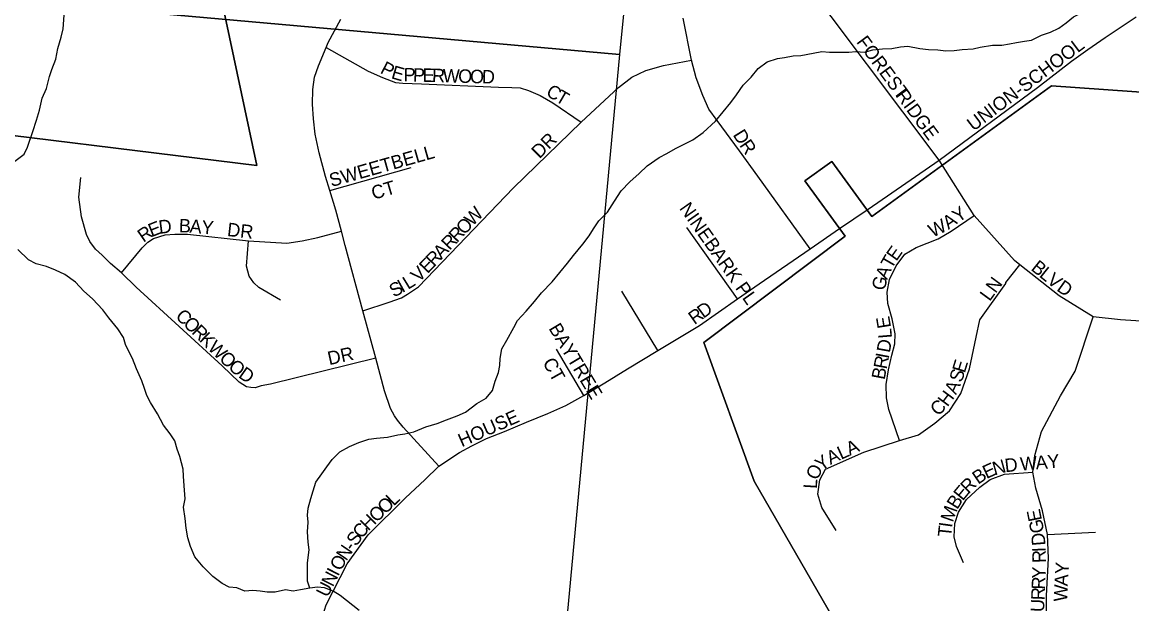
# Model space of a CAD drawing. Extents: x 0 to 680, y 0 to 440.
# Drawn here: x 81.15 to 93.33, y 190.49 to 196.88 of the extents above; entities that cross this region are included whole.
import ezdxf

# ---------------------------------------------------------------- set-up
doc = ezdxf.new("R2010")
doc.units = 0
for name, color, linetype in [('GM_X_City_Street', 7, 'Continuous'), ('GM_X_City_Street_Text', 7, 'Continuous'), ('GM_X_Corporation', 7, 'Continuous'), ('GM_X_Minor_River', 7, 'Continuous'), ('GM_X_Section', 7, 'Continuous')]:
    doc.layers.add(name, color=color, linetype=linetype)

msp = doc.modelspace()

# ---------------------------------------------------------------- linework, layer by layer
at = {"layer": 'GM_X_City_Street'}
for points in [[(91.221, 195.363), (89.636, 197.477), (89.55, 197.598), (88.772, 198.692), (88.323, 199.318), (87.854, 199.993), (87.693, 200.211), (87.593, 200.353), (87.475, 200.491), (87.323, 200.642), (87.18, 200.757), (87.014, 200.885), (86.894, 200.969), (86.863, 200.985), (86.732, 201.055), (86.598, 201.11), (86.411, 201.179), (86.075, 201.245), (85.679, 201.302), (84.892, 201.379), (83.88, 201.481), (83.451, 201.525)], [(85.727, 192.002), (85.336, 192.432), (85.275, 192.507), (85.242, 192.557), (85.198, 192.636), (85.131, 192.831), (85.034, 193.19), (84.893, 193.71), (84.699, 194.428), (84.657, 194.583), (84.595, 194.815), (84.53, 195.03), (84.483, 195.185), (84.414, 195.445), (84.371, 195.65), (84.351, 195.818), (84.341, 195.98), (84.344, 196.141), (84.363, 196.277), (84.405, 196.4), (84.491, 196.602), (84.514, 196.657), (84.652, 196.913)], [(89.804, 194.39), (89.228, 195.189), (89.027, 195.465), (88.782, 195.801), (88.69, 195.923), (88.626, 196.075), (88.553, 196.27), (88.501, 196.462), (88.41, 196.923)], [(90.438, 194.826), (91.221, 195.363), (92.298, 196.161), (92.671, 196.451), (92.85, 196.579), (93.042, 196.712), (93.381, 196.939)], [(84.491, 196.602), (84.95, 196.341), (85.107, 196.273), (85.253, 196.218), (85.33, 196.208), (85.538, 196.203), (86.381, 196.164), (86.53, 196.162), (86.619, 196.158), (86.712, 196.129), (86.841, 196.074), (86.979, 195.995), (87.288, 195.781)], [(84.893, 193.71), (85.183, 193.806), (85.317, 193.853), (85.384, 193.891), (85.502, 193.974), (86.546, 195.059), (87.288, 195.781), (87.699, 196.161), (87.844, 196.277), (88, 196.347), (88.195, 196.402), (88.501, 196.462)], [(84.53, 195.03), (85.423, 195.284)], [(94.473, 192.643), (94.098, 193.121), (93.936, 193.322), (93.718, 193.512), (93.49, 193.594), (93.208, 193.61), (92.909, 193.643), (92.537, 193.873), (92.106, 194.215), (92.045, 194.263), (91.604, 194.755), (91.221, 195.363)], [(85.034, 193.19), (83.879, 192.903), (83.777, 192.885), (83.71, 192.864), (83.663, 192.867), (83.616, 192.875), (83.535, 192.927), (83.348, 193.104), (82.406, 193.971), (82.242, 194.127), (82.123, 194.231), (82.032, 194.319), (81.959, 194.388), (81.897, 194.469), (81.86, 194.549), (81.805, 194.743), (81.775, 194.959), (81.798, 195.172)], [(90.125, 194.613), (90.438, 194.826)], [(90.783, 192.285), (90.668, 192.627), (90.641, 192.753), (90.636, 192.9), (90.662, 193.063), (90.699, 193.221), (90.731, 193.347), (90.736, 193.458), (90.704, 193.621), (90.657, 193.79), (90.647, 193.916), (90.673, 194.053), (90.747, 194.205), (90.841, 194.331), (90.967, 194.405), (91.089, 194.452), (91.21, 194.5), (91.352, 194.584), (91.604, 194.755)], [(82.242, 194.127), (82.471, 194.403), (82.534, 194.465), (82.596, 194.504), (82.723, 194.545), (82.83, 194.551), (82.967, 194.55), (83.636, 194.478), (84.059, 194.454), (84.225, 194.477), (84.4, 194.516), (84.657, 194.583)], [(84.3, 189.767), (84.382, 190.128), (84.492, 190.479), (84.722, 190.93), (84.953, 191.25), (85.362, 191.654), (85.573, 191.854), (85.727, 192.002), (85.953, 192.152), (86.088, 192.225), (86.251, 192.308), (86.449, 192.385), (86.689, 192.488), (86.925, 192.583), (87.12, 192.671), (87.318, 192.779), (87.549, 192.919), (87.799, 193.074), (88.13, 193.275), (88.589, 193.548), (89.007, 193.841), (89.243, 194.007), (89.804, 194.39), (90.125, 194.613)], [(89.007, 193.841), (88.451, 194.623)], [(83.988, 193.828), (83.751, 193.965), (83.695, 194.016), (83.645, 194.09), (83.615, 194.199), (83.636, 194.478)], [(90.089, 191.295), (89.931, 191.548), (89.889, 191.695), (89.91, 191.853), (89.973, 191.969), (90.394, 192.158), (90.783, 192.285), (90.994, 192.348), (91.173, 192.474), (91.331, 192.611), (91.457, 192.8), (91.552, 193.074), (91.625, 193.421), (91.667, 193.611), (91.952, 194.01), (91.952, 194.021), (92.106, 194.215)], [(88.13, 193.275), (87.734, 193.926)], [(92.424, 189.875), (92.398, 190.297), (92.398, 190.579), (92.42, 190.992), (92.409, 191.253), (92.355, 191.514), (92.279, 191.763), (92.246, 191.937), (92.268, 192.122), (92.344, 192.383), (92.55, 192.774), (92.713, 193.045), (92.909, 193.643)], [(87.318, 192.779), (87.018, 193.287)], [(91.486, 190.943), (91.41, 191.122), (91.383, 191.226), (91.393, 191.372), (91.431, 191.497), (91.518, 191.638), (91.665, 191.774), (91.779, 191.856), (91.937, 191.916), (92.246, 191.937)], [(92.409, 191.253), (92.936, 191.28)]]:
    msp.add_lwpolyline(points, dxfattribs=at)
at = {"layer": 'GM_X_Corporation'}
for points in [[(83.951, 205.591), (83.402, 201.12), (80.239, 201.509), (79.822, 197.545), (83.345, 197.112), (83.729, 195.305), (79.918, 195.773), (79.532, 197.595), (67.969, 198.303)], [(67.969, 198.303), (79.532, 197.595), (79.918, 195.773), (83.729, 195.305), (83.345, 197.112), (79.822, 197.545), (80.239, 201.509), (83.402, 201.12), (83.951, 205.591)], [(91.033, 188.638), (89.188, 191.837), (88.635, 193.36), (90.186, 194.53), (89.746, 195.137), (90.04, 195.35), (90.48, 194.744), (92.452, 196.179), (96.031, 195.929), (96.041, 196.129), (96.855, 196.073), (96.84, 195.791), (97.973, 194.39), (99.899, 194.457), (98.982, 195.632), (103.205, 195.338)], [(101.687, 179.172), (103.205, 195.338), (98.982, 195.632), (99.899, 194.457), (97.973, 194.39), (96.84, 195.791), (96.855, 196.073), (96.041, 196.129), (96.031, 195.929), (92.452, 196.179), (90.48, 194.744), (90.04, 195.35), (89.746, 195.137), (90.186, 194.53), (88.635, 193.36), (89.188, 191.837), (91.033, 188.638)]]:
    msp.add_lwpolyline(points, dxfattribs=at)
at = {"layer": 'GM_X_Minor_River'}
for points in [[(92.615, 196.873), (92.693, 196.938), (92.788, 196.986), (92.913, 197.063), (92.99, 197.117), (93.091, 197.194), (93.294, 197.361), (93.377, 197.468)], [(81.074, 195.353), (81.175, 195.43), (81.211, 195.508), (81.27, 195.68), (81.312, 195.805), (81.342, 195.912), (81.372, 196.044), (81.419, 196.151), (81.455, 196.282), (81.479, 196.359), (81.521, 196.472), (81.544, 196.591), (81.58, 196.716), (81.604, 196.806), (81.616, 196.955)], [(84.311, 190.662), (84.287, 190.739), (84.287, 190.941), (84.305, 191.084), (84.293, 191.167), (84.287, 191.281), (84.293, 191.388), (84.287, 191.465), (84.293, 191.543), (84.323, 191.65), (84.347, 191.733), (84.377, 191.828), (84.442, 191.918), (84.496, 191.995), (84.555, 192.078), (84.639, 192.162), (84.746, 192.221), (84.847, 192.263), (84.96, 192.299), (85.043, 192.311), (85.163, 192.323), (85.276, 192.346), (85.353, 192.358), (85.454, 192.382), (85.585, 192.436), (85.71, 192.471), (85.811, 192.513), (85.93, 192.555), (86.02, 192.597), (86.145, 192.692), (86.246, 192.751), (86.317, 192.835), (86.347, 192.936), (86.383, 193.031), (86.395, 193.109), (86.401, 193.186), (86.419, 193.293), (86.472, 193.388), (86.549, 193.525), (86.591, 193.603), (86.686, 193.704), (86.776, 193.811), (86.853, 193.906), (86.972, 194.026), (87.139, 194.234), (87.204, 194.317), (87.306, 194.442), (87.377, 194.532), (87.425, 194.609), (87.484, 194.698), (87.579, 194.794), (87.657, 194.913), (87.728, 195.026), (87.824, 195.127), (87.925, 195.217), (88.014, 195.3), (88.145, 195.395), (88.228, 195.437), (88.324, 195.491), (88.514, 195.586), (88.627, 195.669), (88.764, 195.794), (88.931, 195.997), (88.996, 196.08), (89.068, 196.187), (89.157, 196.277), (89.234, 196.372), (89.33, 196.443), (89.443, 196.479), (89.52, 196.491), (89.615, 196.509), (89.699, 196.515), (89.836, 196.539), (89.931, 196.557), (90.014, 196.551), (90.228, 196.551), (90.306, 196.557), (90.401, 196.551), (90.49, 196.575), (90.597, 196.586), (90.699, 196.592), (90.794, 196.61), (90.877, 196.616), (91.008, 196.592), (91.103, 196.581), (91.205, 196.575), (91.294, 196.563), (91.383, 196.569), (91.472, 196.581), (91.591, 196.587), (91.669, 196.604), (91.806, 196.628), (91.907, 196.628), (91.99, 196.64), (92.068, 196.658), (92.157, 196.67), (92.234, 196.682), (92.341, 196.736), (92.443, 196.771), (92.532, 196.813), (92.615, 196.873)], [(84.853, 190.418), (84.644, 190.584), (84.567, 190.632), (84.472, 190.667), (84.394, 190.673), (84.311, 190.662), (84.21, 190.644), (84.127, 190.632), (84.043, 190.644), (83.93, 190.62), (83.841, 190.62), (83.764, 190.632), (83.686, 190.638), (83.597, 190.632), (83.508, 190.667), (83.424, 190.673), (83.347, 190.715), (83.246, 190.792), (83.139, 190.899), (83.049, 191.007), (83.002, 191.12), (82.972, 191.215), (82.954, 191.322), (82.942, 191.429), (82.924, 191.554), (82.942, 191.644), (82.93, 191.786), (82.925, 191.894), (82.919, 191.971), (82.883, 192.108), (82.853, 192.191), (82.829, 192.281), (82.776, 192.358), (82.704, 192.453), (82.639, 192.578), (82.562, 192.703), (82.52, 192.781), (82.496, 192.858), (82.466, 192.941), (82.407, 193.072), (82.365, 193.185), (82.324, 193.263), (82.288, 193.34), (82.264, 193.418), (82.205, 193.513), (82.103, 193.632), (82.038, 193.721), (81.925, 193.84), (81.83, 193.924), (81.74, 194.025), (81.621, 194.108), (81.52, 194.156), (81.419, 194.198), (81.306, 194.227), (81.223, 194.269), (81.104, 194.382)]]:
    msp.add_lwpolyline(points, dxfattribs=at)
at = {"layer": 'GM_X_Section'}
for points in [[(89.303, 212.485), (87.711, 196.525), (72.033, 197.922), (73.628, 213.785)], [(87.711, 196.525), (86.234, 180.729), (70.5, 182.241), (72.033, 197.922)]]:
    msp.add_lwpolyline(points, close=True, dxfattribs=at)

# ---------------------------------------------------------------- texts
at = {"layer": 'GM_X_City_Street_Text'}
for s, height, rotation, p in [('FOREST', 0.1482, 306.4294, (90.305, 196.662)), ('UNION-SCHOOL', 0.14823, 36.9771, (91.596, 195.677)), ('P', 0.148, 332.4577, (85.074, 196.326)), ('E', 0.148, 343.8402, (85.196, 196.265)), ('P', 0.148, 358.6381, (85.338, 196.23)), ('P', 0.148, 358.4696, (85.442, 196.227)), ('E', 0.148, 358.5497, (85.546, 196.225)), ('R', 0.148, 358.543, (85.651, 196.222)), ('W', 0.148, 358.5372, (85.768, 196.219)), ('O', 0.148, 358.5628, (85.938, 196.215)), ('O', 0.148, 358.5575, (86.068, 196.211)), ('D', 0.148, 358.5357, (86.198, 196.208)), ('C', 0.148, 328.3241, (86.893, 196.082)), ('T', 0.148, 329.8525, (86.996, 196.018)), ('RIDGE', 0.1482, 306.3282, (90.735, 196.075)), ('DR', 0.1482, 45, (86.832, 195.374)), ('D', 0.148, 301.8896, (88.95, 195.643)), ('SWEETBELL', 0.1482, 15.7502, (84.548, 195.068)), ('R', 0.148, 303.831, (89.021, 195.528)), ('CT', 0.1482, 16.3944, (85.011, 194.928)), ('NINEBARK PL', 0.14823, 305.0977, (88.361, 194.835)), ('W', 0.148, 46.3938, (86.097, 194.631)), ('Y', 0.148, 35.1648, (91.429, 194.673)), ('E', 0.148, 21.7456, (82.573, 194.517)), ('D', 0.148, 7.3852, (82.661, 194.554)), ('B', 0.148, 358.3482, (82.872, 194.572)), ('A', 0.148, 355.3616, (82.987, 194.568)), ('Y', 0.148, 354.8135, (83.117, 194.558)), ('DR', 0.1482, 353.6505, (83.398, 194.532)), ('O', 0.148, 46.3911, (86.007, 194.536)), ('W', 0.148, 26.0387, (91.147, 194.511)), ('A', 0.148, 34.9396, (91.321, 194.598)), ('R', 0.148, 34.451, (82.484, 194.455)), ('R', 0.148, 46.3987, (85.846, 194.366)), ('R', 0.148, 46.4081, (85.926, 194.451)), ('A', 0.148, 46.3911, (85.756, 194.272)), ('E', 0.148, 54.529, (90.748, 194.247)), ('E', 0.148, 46.4313, (85.603, 194.111)), ('R', 0.148, 46.3913, (85.675, 194.187)), ('T', 0.148, 60.1467, (90.698, 194.16)), ('V', 0.148, 44.5691, (85.506, 194.016)), ('A', 0.148, 66.2217, (90.647, 194.044)), ('B', 0.148, 321.435, (92.218, 194.163)), ('L', 0.148, 321.4085, (92.309, 194.09)), ('I', 0.148, 29.0886, (85.325, 193.904)), ('L', 0.148, 31.5702, (85.388, 193.939)), ('G', 0.148, 76.9234, (90.62, 193.924)), ('LN', 0.1482, 53.7411, (91.773, 193.806)), ('V', 0.148, 321.4372, (92.391, 194.025)), ('D', 0.148, 324.7763, (92.5, 193.938)), ('S', 0.148, 29.0944, (85.234, 193.853)), ('D', 0.148, 36.1692, (88.631, 193.621)), ('C', 0.148, 315.7213, (82.827, 193.64)), ('R', 0.148, 35.3542, (88.533, 193.552)), ('O', 0.148, 315.7482, (82.912, 193.557)), ('R', 0.148, 315.7213, (83.005, 193.467)), ('BAYTREE', 0.1482, 300.9643, (86.928, 193.517)), ('E', 0.148, 99.2351, (90.692, 193.529)), ('K', 0.148, 315.7323, (83.089, 193.384)), ('L', 0.148, 94.7142, (90.702, 193.412)), ('W', 0.148, 315.7287, (83.182, 193.293)), ('DR', 0.1482, 12.5327, (84.524, 193.112)), ('D', 0.148, 79.9575, (90.677, 193.243)), ('O', 0.148, 317.3105, (83.307, 193.172)), ('CT', 0.1482, 299.3565, (86.862, 193.143)), ('R', 0.148, 79.1521, (90.642, 193.062)), ('I', 0.148, 79.1619, (90.664, 193.177)), ('O', 0.148, 318.9883, (83.406, 193.08)), ('D', 0.148, 324.773, (83.518, 192.985)), ('B', 0.148, 79.1521, (90.62, 192.946)), ('S', 0.148, 71.1673, (91.465, 192.915)), ('E', 0.148, 72.9291, (91.5, 193.019)), ('H', 0.148, 53.6051, (91.31, 192.648)), ('A', 0.148, 65.0874, (91.404, 192.781)), ('C', 0.148, 42.973, (91.204, 192.546)), ('HOUSE', 0.1482, 23.8399, (85.979, 192.21)), ('L', 0.148, 24.5118, (90.142, 192.072)), ('A', 0.148, 24.5018, (90.237, 192.116)), ('Y', 0.148, 36.3279, (89.926, 191.943)), ('A', 0.148, 25.6071, (90.025, 192.016)), ('D', 0.148, 6.2412, (91.946, 191.936)), ('W', 0.148, 4.7794, (92.114, 191.953)), ('A', 0.148, 4.7491, (92.283, 191.967)), ('Y', 0.148, 4.7792, (92.413, 191.978)), ('O', 0.148, 62.7311, (89.878, 191.84)), ('B', 0.148, 34.3434, (91.647, 191.798)), ('E', 0.148, 24.5728, (91.738, 191.861)), ('N', 0.148, 15.7172, (91.827, 191.902)), ('L', 0.148, 86.4185, (89.876, 191.752)), ('R', 0.148, 44.9313, (91.54, 191.693)), ('E', 0.148, 50.5722, (91.477, 191.615)), ('O', 0.148, 44.0595, (85.138, 191.469)), ('L', 0.148, 44.0704, (85.231, 191.559)), ('B', 0.148, 57.6573, (91.417, 191.52)), ('H', 0.148, 44.7991, (84.952, 191.286)), ('O', 0.148, 44.0573, (85.044, 191.378)), ('M', 0.148, 70.3094, (91.368, 191.38)), ('E', 0.148, 101.3047, (92.349, 191.412)), ('C', 0.148, 50.7977, (84.88, 191.198)), ('I', 0.148, 82.1049, (91.361, 191.323)), ('G', 0.148, 100.5468, (92.374, 191.281)), ('S', 0.148, 54.5105, (84.821, 191.115)), ('T', 0.148, 84.197, (91.35, 191.221)), ('D', 0.148, 94.7345, (92.387, 191.135)), ('N', 0.148, 55.819, (84.711, 190.955)), ('-', 0.148, 54.503, (84.783, 191.062)), ('O', 0.148, 61.5675, (84.651, 190.844)), ('I', 0.148, 92.0977, (92.389, 191.062)), ('R', 0.148, 90.7421, (92.391, 190.941)), ('I', 0.148, 63.3372, (84.622, 190.787)), ('Y', 0.148, 87.9015, (92.385, 190.764)), ('Y', 0.148, 86.3037, (92.638, 190.812)), ('N', 0.148, 63.3341, (84.563, 190.67)), ('R', 0.148, 87.9112, (92.381, 190.646)), ('A', 0.148, 86.4564, (92.63, 190.682)), ('U', 0.148, 63.347, (84.505, 190.554)), ('R', 0.148, 87.9112, (92.376, 190.529)), ('W', 0.148, 87.4944, (92.623, 190.513)), ('U', 0.148, 87.9099, (92.371, 190.399))]:
    msp.add_text(s, height=height, rotation=rotation, dxfattribs=at).set_placement(p)

doc.saveas('drawing.dxf')
